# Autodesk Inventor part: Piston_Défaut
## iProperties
Shininess: 64.0
Length Units: 11269
Angle Units: 11279
Time Units: 11290
Mass Units: 11283
Length Display Precision: 3
Angle Display Precision: 2
Compacted: True
Part Number: Piston_Défaut
Document SubType Name: Modeling
Created: 2006-01
Material: Par défaut
Designer: riri
Density: 0.0
Volumn: 0.0
Area: 0.0
PropertySet Name: Model Information
Control State: 0
Master: False
Checked Out: False
Author: riri
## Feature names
1. Base1
